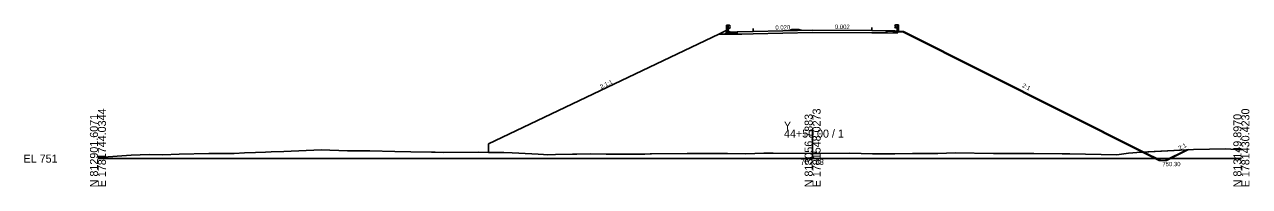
# Model space of a CAD drawing. Extents: x -12583 to 5303, y -44 to 25667.
# Drawn here: x 2874.3 to 3302.8, y 4990.3 to 5046.8 of the extents above; entities that cross this region are included whole.
import ezdxf

# ---------------------------------------------------------------- set-up
doc = ezdxf.new("R2010")
doc.units = 0
for name, color, linetype in [('Exist Cross Section Cell', 7, 'Continuous'), ('Exist XS Center Line Elevation Label', 7, 'Continuous'), ('Exist XS Ground Line', 7, 'Continuous'), ('Prop Conc 5in Monolithic Surface Mount Island', 7, 'Continuous'), ('Prop XS Ditch Standard Text', 7, 'Continuous'), ('Prop XS Dump Level', 7, 'Continuous'), ('Prop XS Earthwork Shape', 7, 'Continuous'), ('Prop XS EOT Tick Mark', 7, 'Continuous'), ('Prop XS Finish Grade', 7, 'Continuous'), ('Prop XS Finish Grade CurbGutter', 7, 'Continuous'), ('Prop XS Finish Grade Earthwork', 7, 'Continuous'), ('Prop XS Finish Grade Paved Shoulder', 7, 'Continuous'), ('Prop XS Finish Grade Pavement', 7, 'Continuous'), ('Prop XS Guardrail', 7, 'Continuous'), ('Prop XS Pvmt Edge Slope', 7, 'Continuous'), ('Prop XS SE Text', 7, 'Continuous'), ('Prop XS Side Slope Text', 7, 'Continuous'), ('Prop XS Subgrade CurbGutter', 7, 'Continuous'), ('Prop XS Subgrade Earthwork', 7, 'Continuous')]:
    doc.layers.add(name, color=color, linetype=linetype)

msp = doc.modelspace()

# ---------------------------------------------------------------- linework, layer by layer
at = {"layer": 'Exist Cross Section Cell'}
for p, q in [((3150, 5000), (3150, 5010.13)), ((2900, 5000), (3150, 5000)), ((3150, 5000), (3300, 5000))]:
    msp.add_line(p, q, dxfattribs=at)
at = {"layer": 'Exist XS Ground Line'}
for p, q in [((2900.35, 5000.44), (2911.58, 5001.24)), ((2911.58, 5001.24), (2917.89, 5001.42)), ((2917.89, 5001.42), (2922.74, 5001.3)), ((2922.74, 5001.3), (2928.38, 5001.54)), ((2928.38, 5001.54), (2938.81, 5001.77)), ((2938.81, 5001.77), (2947.63, 5001.84)), ((2947.63, 5001.84), (2951.22, 5002.03)), ((2951.22, 5002.03), (2955.12, 5002.09)), ((2955.12, 5002.09), (2958.64, 5002.27)), ((2958.64, 5002.27), (2960.59, 5002.32)), ((2960.59, 5002.32), (2965.04, 5002.5)), ((2965.04, 5002.5), (2978.05, 5003.06)), ((2978.05, 5003.06), (2987.27, 5002.75)), ((2987.27, 5002.75), (2992.46, 5002.72)), ((2992.46, 5002.72), (2995.17, 5002.67)), ((2995.17, 5002.67), (3003.84, 5002.48)), ((3003.84, 5002.48), (3009.46, 5002.42)), ((3009.46, 5002.42), (3016.65, 5002.25)), ((3016.65, 5002.25), (3017.97, 5002.21)), ((3017.97, 5002.21), (3020.71, 5002.14)), ((3020.71, 5002.14), (3032.98, 5002.22)), ((3032.98, 5002.22), (3042.03, 5002.11)), ((3042.03, 5002.11), (3044.91, 5002.05)), ((3044.91, 5002.05), (3047.21, 5001.92)), ((3047.21, 5001.92), (3054, 5001.51)), ((3054, 5001.51), (3055.85, 5001.39)), ((3055.85, 5001.39), (3057.32, 5001.38)), ((3057.32, 5001.38), (3060.01, 5001.42)), ((3060.01, 5001.42), (3066.04, 5001.51)), ((3066.04, 5001.51), (3067.5, 5001.52)), ((3067.5, 5001.52), (3072.48, 5001.66)), ((3072.48, 5001.66), (3077.77, 5001.54)), ((3077.77, 5001.54), (3081.84, 5001.52)), ((3081.84, 5001.52), (3083.52, 5001.52)), ((3083.52, 5001.52), (3091.31, 5001.58)), ((3091.31, 5001.58), (3093.13, 5001.63)), ((3093.13, 5001.63), (3093.59, 5001.63)), ((3093.59, 5001.63), (3106.09, 5001.83)), ((3106.09, 5001.83), (3108.72, 5001.83)), ((3108.72, 5001.83), (3115.14, 5001.83)), ((3115.14, 5001.83), (3120.27, 5001.81)), ((3120.27, 5001.81), (3126.7, 5001.73)), ((3126.7, 5001.73), (3132.94, 5001.85)), ((3132.94, 5001.85), (3136.23, 5001.86)), ((3136.23, 5001.86), (3150.27, 5001.83)), ((3150.27, 5001.83), (3151.25, 5001.82)), ((3151.25, 5001.82), (3151.56, 5001.84)), ((3151.56, 5001.84), (3152.25, 5001.82)), ((3152.25, 5001.82), (3163.01, 5001.93)), ((3163.01, 5001.93), (3171.01, 5001.65)), ((3171.01, 5001.65), (3174.32, 5001.69)), ((3174.32, 5001.69), (3178.8, 5001.65)), ((3178.8, 5001.65), (3184.96, 5001.83)), ((3184.96, 5001.83), (3193.79, 5001.84)), ((3193.79, 5001.84), (3196.85, 5001.88)), ((3196.85, 5001.88), (3199.89, 5001.97)), ((3199.89, 5001.97), (3213.28, 5001.84)), ((3213.28, 5001.84), (3220.05, 5001.78)), ((3220.05, 5001.78), (3227.39, 5001.76)), ((3227.39, 5001.76), (3237.31, 5001.73)), ((3237.31, 5001.73), (3238.84, 5001.71)), ((3238.84, 5001.71), (3240, 5001.68)), ((3240, 5001.68), (3256.43, 5001.33)), ((3256.43, 5001.33), (3260.54, 5001.91)), ((3260.54, 5001.91), (3264.89, 5002.22)), ((3264.89, 5002.22), (3283.21, 5003.24)), ((3283.21, 5003.24), (3294.46, 5003.38)), ((3294.46, 5003.38), (3300, 5003.05)), ((2900, 5000.43), (2900.35, 5000.44))]:
    msp.add_line(p, q, dxfattribs=at)
at = {"layer": 'Prop Conc 5in Monolithic Surface Mount Island'}
for p, q in [((3142, 5044.75), (3142.74, 5045.02)), ((3142, 5044.59), (3142, 5044.75)), ((3142.74, 5045.02), (3143.99, 5045.07)), ((3145.24, 5045.07), (3143.99, 5045.07)), ((3146, 5044.83), (3145.24, 5045.07)), ((3146, 5044.67), (3146, 5044.83))]:
    msp.add_line(p, q, dxfattribs=at)
at = {"layer": 'Prop XS Dump Level'}
for p, q in [((3129.25, 5044.33), (3150, 5044.75)), ((3150, 5044.75), (3170.75, 5044.71))]:
    msp.add_line(p, q, dxfattribs=at)
at = {"layer": 'Prop XS Earthwork Shape'}
for points in [[(3106.09, 5001.83), (3108.72, 5001.83), (3115.14, 5001.83), (3120.27, 5001.81), (3126.7, 5001.73), (3132.94, 5001.85), (3136.23, 5001.86), (3150.27, 5001.83), (3151.25, 5001.82), (3151.56, 5001.84), (3152.25, 5001.82), (3163.01, 5001.93), (3171.01, 5001.65), (3174.32, 5001.69), (3178.8, 5001.65), (3184.96, 5001.83), (3193.79, 5001.84), (3196.85, 5001.88), (3199.89, 5001.97), (3213.28, 5001.84), (3220.05, 5001.78), (3227.39, 5001.76), (3237.31, 5001.73), (3238.84, 5001.71), (3240, 5001.68), (3256.43, 5001.33), (3260.54, 5001.91), (3264.89, 5002.22), (3265.39, 5002.25), (3181.75, 5044.07), (3176.25, 5044.51), (3175.56, 5043.82), (3174.75, 5043.84), (3170.75, 5043.92), (3150, 5043.96), (3129.25, 5043.54), (3125.25, 5043.46), (3123.58, 5043.42), (3119.19, 5043.42), (3117.18, 5043.42), (3036.65, 5005.14), (3036.65, 5002.18), (3042.03, 5002.11), (3044.91, 5002.05), (3047.21, 5001.92), (3054, 5001.51), (3055.85, 5001.39), (3057.32, 5001.38), (3060.01, 5001.42), (3066.04, 5001.51), (3067.5, 5001.52), (3072.48, 5001.66), (3077.77, 5001.54), (3081.84, 5001.52), (3083.52, 5001.52), (3091.31, 5001.58), (3093.13, 5001.63), (3093.59, 5001.63)], [(3271.29, 4999.3), (3273.29, 4999.3), (3280.93, 5003.12), (3265.39, 5002.25)]]:
    msp.add_lwpolyline(points, close=True, dxfattribs=at)
at = {"layer": 'Prop XS EOT Tick Mark'}
for p, q in [((3129.25, 5044.33), (3129.25, 5045.33)), ((3170.75, 5044.71), (3170.75, 5045.71))]:
    msp.add_line(p, q, dxfattribs=at)
at = {"layer": 'Prop XS Finish Grade'}
for p, q in [((3119.98, 5044.76), (3117.18, 5043.42)), ((3120.56, 5044.47), (3119.98, 5044.76)), ((3178.75, 5044.55), (3180.25, 5044.43))]:
    msp.add_line(p, q, dxfattribs=at)
at = {"layer": 'Prop XS Finish Grade CurbGutter'}
for p, q in [((3121.25, 5044.13), (3120.56, 5044.47)), ((3123.58, 5044.22), (3121.25, 5044.13))]:
    msp.add_line(p, q, dxfattribs=at)
at = {"layer": 'Prop XS Finish Grade Earthwork'}
for p, q in [((3180.25, 5044.43), (3181.75, 5044.31)), ((3181.75, 5044.31), (3265.82, 5002.27)), ((3117.18, 5043.42), (3036.65, 5005.14)), ((3036.65, 5005.14), (3036.65, 5002.18)), ((3265.82, 5002.27), (3271.77, 4999.3)), ((3273.77, 4999.3), (3281.47, 5003.15)), ((3271.77, 4999.3), (3273.77, 4999.3))]:
    msp.add_line(p, q, dxfattribs=at)
at = {"layer": 'Prop XS Finish Grade Paved Shoulder'}
for p, q in [((3129.25, 5044.33), (3123.58, 5044.22)), ((3170.75, 5044.71), (3178.75, 5044.55))]:
    msp.add_line(p, q, dxfattribs=at)
at = {"layer": 'Prop XS Finish Grade Pavement'}
for p, q in [((3129.25, 5044.33), (3150, 5044.75)), ((3150, 5044.75), (3170.75, 5044.71)), ((3150, 5044.75), (3170.75, 5044.71))]:
    msp.add_line(p, q, dxfattribs=at)
at = {"layer": 'Prop XS Guardrail'}
for p, q in [((3119.93, 5046.52), (3120.43, 5046.52)), ((3119.93, 5044.02), (3119.93, 5046.52)), ((3120.43, 5046.52), (3120.93, 5046.52)), ((3120.43, 5046.52), (3120.43, 5044.02)), ((3120.93, 5045.39), (3120.43, 5045.39)), ((3120.93, 5046.52), (3121.22, 5046.32)), ((3121.22, 5046.2), (3120.93, 5046)), ((3120.93, 5046), (3120.93, 5045.91)), ((3120.93, 5045.91), (3121.22, 5045.71)), ((3121.22, 5045.59), (3120.93, 5045.39)), ((3121.22, 5046.32), (3121.25, 5046.26)), ((3121.25, 5046.26), (3121.22, 5046.2)), ((3121.22, 5045.71), (3121.25, 5045.65)), ((3121.25, 5045.65), (3121.22, 5045.59)), ((3178.78, 5046.51), (3178.75, 5046.45)), ((3178.75, 5046.45), (3178.78, 5046.39)), ((3178.78, 5045.89), (3178.75, 5045.83)), ((3178.75, 5045.83), (3178.78, 5045.77)), ((3179.07, 5046.71), (3178.78, 5046.51)), ((3178.78, 5046.39), (3179.07, 5046.19)), ((3179.07, 5046.09), (3178.78, 5045.89)), ((3178.78, 5045.77), (3179.07, 5045.57)), ((3179.57, 5046.71), (3179.07, 5046.71)), ((3179.07, 5046.19), (3179.07, 5046.09)), ((3179.07, 5045.57), (3179.57, 5045.57)), ((3180.07, 5046.71), (3179.57, 5046.71)), ((3179.57, 5046.71), (3179.57, 5044.21)), ((3180.07, 5044.21), (3180.07, 5046.71))]:
    msp.add_line(p, q, dxfattribs=at)
at = {"layer": 'Prop XS Pvmt Edge Slope'}
for p, q in [((3178.75, 5044.55), (3179.56, 5043.74)), ((3119.56, 5043.8), (3119.19, 5043.42)), ((3120.56, 5043.8), (3119.56, 5043.8))]:
    msp.add_line(p, q, dxfattribs=at)
at = {"layer": 'Prop XS Subgrade CurbGutter'}
for p, q in [((3120.56, 5043.8), (3120.56, 5044.47)), ((3123.58, 5044.22), (3123.58, 5043.8)), ((3123.58, 5043.8), (3120.56, 5043.8))]:
    msp.add_line(p, q, dxfattribs=at)
at = {"layer": 'Prop XS Subgrade Earthwork'}
for p, q in [((3150, 5043.96), (3129.25, 5043.54)), ((3170.75, 5043.92), (3150, 5043.96)), ((3170.75, 5043.92), (3174.75, 5043.84)), ((3174.75, 5043.84), (3179.56, 5043.74)), ((3179.56, 5043.74), (3180.25, 5044.43)), ((3119.19, 5043.42), (3117.18, 5043.42)), ((3123.58, 5043.42), (3119.19, 5043.42)), ((3125.25, 5043.46), (3123.58, 5043.42)), ((3129.25, 5043.54), (3125.25, 5043.46))]:
    msp.add_line(p, q, dxfattribs=at)

# ---------------------------------------------------------------- texts
at = {"layer": 'Exist Cross Section Cell'}
for s, p in [('N 812901.6071', (2900, 4990)), ('E 1781744.0344', (2902.8, 4990)), ('N 813056.7883', (3150, 4990)), ('E 1781548.0273', (3152.8, 4990)), ('N 813149.8970', (3300, 4990)), ('E 1781430.4230', (3302.8, 4990))]:
    msp.add_text(s, height=2.8, rotation=90, dxfattribs=at).set_placement(p)
for s, p in [('Y', (3140, 5010.13)), ('44+50.00 / 1', (3140, 5007.33)), ('EL 751', (2874, 4998.6))]:
    msp.add_text(s, height=2.8, dxfattribs=at).set_placement(p)
at = {"layer": 'Exist XS Center Line Elevation Label'}
msp.add_text('752.83', height=2, dxfattribs=at).set_placement((3145.75, 4997.83))
at = {"layer": 'Prop XS Ditch Standard Text'}
msp.add_text('750.30', height=1.5, dxfattribs=at).set_placement((3272.38, 4997.37))
at = {"layer": 'Prop XS Dump Level'}
msp.add_text('Case2', height=0.04, dxfattribs=at).set_placement((3178.75, 5044.27))
at = {"layer": 'Prop XS SE Text'}
for s, rotation, p in [('0.020', 1.1458, (3137, 5044.99)), ('0.002', 359.8963, (3157.81, 5045.23)), ('0.002', 359.8963, (3157.81, 5045.23))]:
    msp.add_text(s, height=1.5, rotation=rotation, dxfattribs=at).set_placement(p)
at = {"layer": 'Prop XS Side Slope Text'}
for s, rotation, p in [('2.1:1', 26.5651, (3076.08, 5024.28)), ('2:1', 333.4349, (3223.16, 5025.04)), ('2:1', 26.5651, (3278.38, 5002.89))]:
    msp.add_text(s, height=1.5, rotation=rotation, dxfattribs=at).set_placement(p)

doc.saveas('drawing.dxf')
